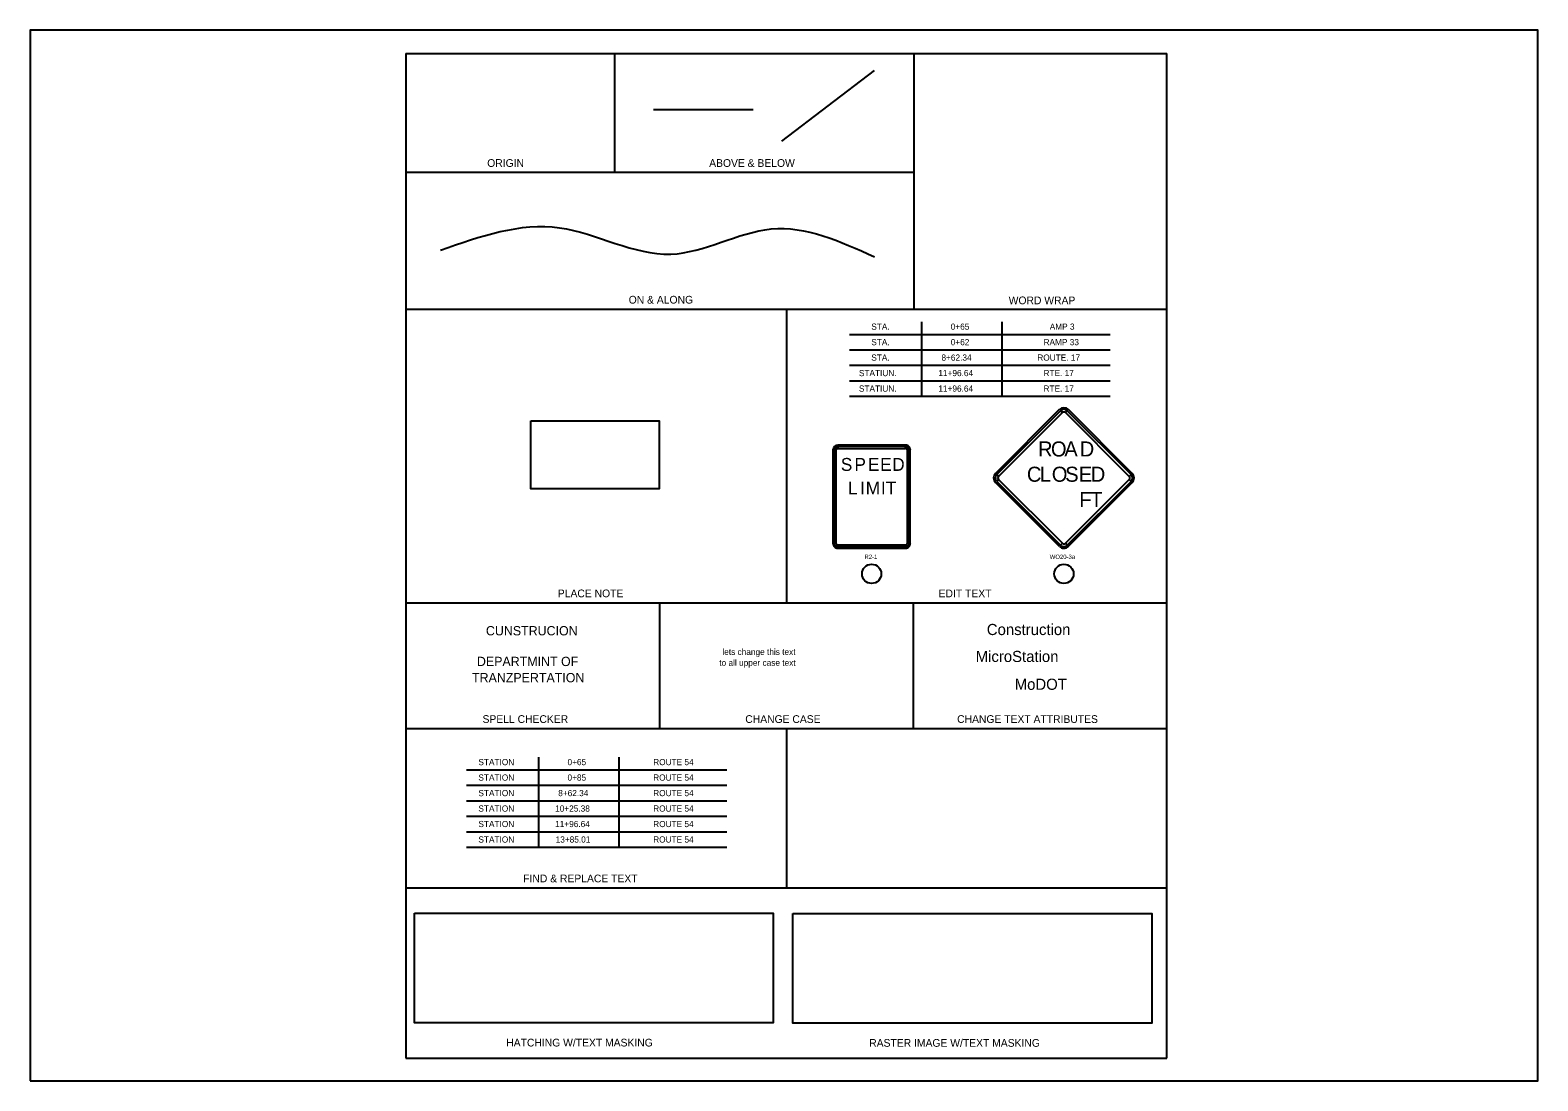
# Model space of a CAD drawing. Extents: x -1524 to 1400, y -1030 to 1008.
import ezdxf

# ---------------------------------------------------------------- set-up
doc = ezdxf.new("R2010")
doc.units = 0
for name, color, linetype in [('Common-Notes', 7, 'Continuous'), ('Draft_Named_Boundary', 7, 'Continuous'), ('Level 1', 7, 'Continuous'), ('Level 2', 7, 'Continuous'), ('Level 25', 7, 'Continuous'), ('Roadway-Signs', 7, 'Continuous')]:
    doc.layers.add(name, color=color, linetype=linetype)

msp = doc.modelspace()

# ---------------------------------------------------------------- linework, layer by layer
at = {"layer": 'Draft_Named_Boundary'}
msp.add_lwpolyline([(-1524.4, -1029.6), (1399.8, -1029.6), (1399.8, 1007.9), (-1524.4, 1007.9)], close=True, dxfattribs=at)
at = {"layer": 'Level 1'}
for p, q in [((-795.5, 962.8), (680.1, 962.8)), ((-795.5, 962.8), (-795.5, -985.9)), ((-391, 962.8), (-391, 732.3)), ((189.4, 962.8), (189.4, 467.2)), ((680.1, -985.9), (680.1, 962.8)), ((-795.5, 732.3), (189.4, 732.3)), ((-795.5, 467.2), (680.1, 467.2)), ((-57.7, 467.2), (-57.7, -102.3)), ((126.8, 433), (126.8, 433)), ((282.6, 433), (282.6, 433)), ((480.5, 433), (480.5, 433)), ((126.8, 403), (126.8, 403)), ((282.6, 403), (282.6, 403)), ((480.5, 403), (480.5, 403)), ((126.8, 373), (126.8, 373)), ((282.6, 373), (282.6, 373)), ((480.5, 373), (480.5, 373)), ((126.8, 343), (126.8, 343)), ((282.6, 343), (282.6, 343)), ((480.5, 343), (480.5, 343)), ((126.8, 312.9), (126.8, 312.9)), ((282.6, 312.9), (282.6, 312.9)), ((480.5, 312.9), (480.5, 312.9)), ((-795.5, -102.3), (680.1, -102.3)), ((-303.6, -102.3), (-303.6, -346)), ((188.3, -102.3), (188.3, -346)), ((-795.5, -346), (680.1, -346)), ((-57.7, -346), (-57.7, -655.1)), ((-795.5, -655.1), (680.1, -655.1)), ((-795.5, -985.9), (680.1, -985.9))]:
    msp.add_line(p, q, dxfattribs=at)
for points in [[(-779.2, -704.7), (-83.3, -704.7), (-83.3, -917.2), (-779.2, -917.2)], [(-45, -705.3), (651, -705.3), (651, -917.8), (-45, -917.8)]]:
    msp.add_lwpolyline(points, close=True, dxfattribs=at)
at = {"layer": 'Level 2'}
for p, q in [((204.7, 442.5), (204.7, 297.9)), ((360.5, 442.5), (360.5, 297.9)), ((65, 418), (570, 418)), ((65, 388), (570, 388)), ((65, 358), (570, 358)), ((65, 328), (570, 328)), ((65, 297.9), (570, 297.9)), ((-538.6, -401.9), (-538.6, -576.5)), ((-382.8, -401.9), (-382.8, -576.5)), ((-678.2, -426.4), (-173.3, -426.4)), ((-678.2, -456.4), (-173.3, -456.4)), ((-678.2, -486.5), (-173.3, -486.5)), ((-678.2, -516.5), (-173.3, -516.5)), ((-678.2, -546.5), (-173.3, -546.5)), ((-678.2, -576.5), (-173.3, -576.5))]:
    msp.add_line(p, q, dxfattribs=at)
at = {"layer": 'Level 25'}
for p, q in [((-66.7, 792.5), (113.2, 930)), ((-315.7, 854.4), (-122.4, 854.4))]:
    msp.add_line(p, q, dxfattribs=at)
msp.add_lwpolyline([(-553.1, 250.6), (-304.6, 250.6), (-304.6, 118.8), (-553.1, 118.8)], close=True, dxfattribs=at)
msp.add_spline([(-728.3, 581.3), (-497.5, 624.9), (-282, 573.6), (-87.1, 622.4), (113, 568.5)], degree=3, dxfattribs=at)
at = {"layer": 'Roadway-Signs'}
for p, q in [((471.7, 272.1), (348, 148.4)), ((473.9, 269.9), (477.6, 266.2)), ((483.5, 266.2), (487.2, 269.9)), ((613.1, 148.4), (489.4, 272.1)), ((32.7, 193.9), (32.7, 12.7)), ((35.3, 193.9), (39, 193.9)), ((173.4, 203.3), (42.1, 203.3)), ((42.1, 197), (42.1, 200.7)), ((173.4, 200.7), (173.4, 197)), ((176.5, 193.9), (180.1, 193.9)), ((182.7, 12.7), (182.7, 193.9)), ((348, 130.7), (471.7, 7)), ((353.9, 142.5), (350.2, 146.2)), ((350.2, 132.9), (353.9, 136.6)), ((489.4, 7), (613.1, 130.7)), ((610.9, 146.2), (607.3, 142.5)), ((607.3, 136.6), (610.9, 132.9)), ((39, 12.7), (35.3, 12.7)), ((42.1, 5.9), (42.1, 9.5)), ((42.1, 3.3), (173.4, 3.3)), ((173.4, 9.5), (173.4, 5.9)), ((180.1, 12.7), (176.5, 12.7)), ((477.6, 12.8), (473.9, 9.2)), ((487.2, 9.2), (483.5, 12.8))]:
    msp.add_line(p, q, dxfattribs=at)
for points in [[(473.9, 269.9), (350.2, 146.2), (353.9, 142.5), (477.6, 266.2), (473.9, 269.9)], [(610.9, 146.2), (487.2, 269.9), (483.5, 266.2), (607.3, 142.5), (610.9, 146.2)], [(35.3, 193.9), (35.3, 12.7), (39, 12.7), (39, 193.9), (35.3, 193.9)], [(173.4, 200.7), (42.1, 200.7), (42.1, 197), (173.4, 197), (173.4, 200.7)], [(180.1, 12.7), (180.1, 193.9), (176.5, 193.9), (176.5, 12.7), (180.1, 12.7)], [(350.2, 132.9), (473.9, 9.2), (477.6, 12.8), (353.9, 136.6), (350.2, 132.9)], [(487.2, 9.2), (610.9, 132.9), (607.3, 136.6), (483.5, 12.8), (487.2, 9.2)], [(42.1, 5.9), (173.4, 5.9), (173.4, 9.5), (42.1, 9.5), (42.1, 5.9)]]:
    msp.add_lwpolyline(points, close=True, dxfattribs=at)
for centre in [(107.7, -46.4), (480.6, -46.4)]:
    msp.add_circle(centre, 18.7, dxfattribs=at)
for centre, radius, start, end in [((480.6, 263.3), 12.5, 45, 134.9997), ((480.6, 263.3), 9.37, 45, 134.9997), ((480.6, 263.3), 4.17, 45, 134.9997), ((42.1, 193.9), 9.38, 90.0002, 179.9998), ((42.1, 193.9), 6.77, 90.0002, 179.9998), ((42.1, 193.9), 3.13, 90.0002, 179.9998), ((173.4, 193.9), 9.38, 0, 90.0002), ((173.4, 193.9), 6.77, 0, 90.0002), ((173.4, 193.9), 3.13, 0, 90.0002), ((356.8, 139.5), 12.5, 134.9997, 225), ((604.3, 139.5), 12.5, 315.0002, 44.9998), ((356.8, 139.5), 9.37, 134.9997, 225), ((356.8, 139.5), 4.17, 134.9997, 225), ((604.3, 139.5), 4.17, 315.0002, 44.9998), ((604.3, 139.5), 9.37, 315.0002, 44.9998), ((42.1, 12.7), 9.38, 179.9998, 270.0001), ((42.1, 12.7), 6.77, 179.9998, 270.0001), ((42.1, 12.7), 3.13, 179.9998, 270.0001), ((173.4, 12.7), 9.38, 270.0001, 0.0003), ((173.4, 12.7), 6.77, 270.0001, 0.0003), ((173.4, 12.7), 3.13, 270.0001, 0.0003), ((480.6, 15.8), 12.5, 225, 315.0002), ((480.6, 15.8), 9.37, 225, 315.0002), ((480.6, 15.8), 4.17, 225, 315.0002)]:
    msp.add_arc(centre, radius, start, end, dxfattribs=at)

# ---------------------------------------------------------------- texts
at = {"layer": 'Common-Notes'}
for s, p in [('HATCHING W/TEXT MASKING', (-601, -962.9)), ('RASTER IMAGE W/TEXT MASKING', (103, -963.5))]:
    msp.add_text(s, height=15, dxfattribs=at).set_placement(p)
at = {"layer": 'Level 1'}
for s, p in [('lets change this text', (-181.8, -203.7)), ('to all upper case text', (-187.8, -224.7))]:
    msp.add_text(s, height=12, dxfattribs=at).set_placement(p)
at = {"layer": 'Level 2'}
for s, height, p in [('ORIGIN', 15, (-637.9, 742.8)), ('ABOVE & BELOW', 15, (-207.4, 742.8)), ('ON & ALONG', 15, (-363.5, 477.7)), ('WORD WRAP', 15, (373.5, 476.4)), ('STA.', 12, (107, 427)), ('0+65', 12, (261.1, 427)), ('AMP 3', 12, (453.1, 427)), ('STA.', 12, (107, 397)), ('0+62', 12, (261.1, 397)), ('RAMP 33', 12, (441.1, 397)), ('STA.', 12, (107, 367)), ('8+62.34', 12, (243.1, 367)), ('ROUTE. 17', 12, (429, 367)), ('STATIUN.', 12, (83, 337)), ('11+96.64', 12, (237.1, 337)), ('RTE. 17', 12, (441, 337)), ('STATIUN.', 12, (83, 306.9)), ('11+96.64', 12, (237.1, 306.9)), ('RTE. 17', 12, (441, 306.9)), ('PLACE NOTE', 15, (-501, -91.8)), ('EDIT TEXT', 15, (237.6, -91.8)), ('Construction', 21.6, (331.1, -165.1)), ('CUNSTRUCION', 18, (-640.4, -165.7)), ('MicroStation', 21.6, (309.5, -217.3)), ('DEPARTMINT OF', 18, (-657.9, -225.2)), ('TRANZPERTATION', 18, (-667.4, -256.7)), ('MoDOT', 21.6, (385.2, -271.3)), ('SPELL CHECKER', 15, (-647, -335.5)), ('CHANGE CASE', 15, (-137.4, -335.5)), ('CHANGE TEXT ATTRIBUTES', 15, (273.5, -335.5)), ('STATION', 12, (-655, -417.4)), ('0+65', 12, (-482.2, -417.4)), ('ROUTE 54', 12, (-316, -417.4)), ('STATION', 12, (-655, -447.4)), ('0+85', 12, (-482.2, -447.4)), ('ROUTE 54', 12, (-316, -447.4)), ('STATION', 12, (-655, -477.5)), ('8+62.34', 12, (-500.2, -477.5)), ('ROUTE 54', 12, (-316, -477.5)), ('STATION', 12, (-655, -507.5)), ('10+25.38', 12, (-506.2, -507.5)), ('ROUTE 54', 12, (-316, -507.5)), ('STATION', 12, (-655, -537.5)), ('11+96.64', 12, (-506.2, -537.5)), ('ROUTE 54', 12, (-316, -537.5)), ('STATION', 12, (-655, -567.5)), ('13+85.01', 12, (-505.2, -567.5)), ('ROUTE 54', 12, (-316, -567.5)), ('FIND & REPLACE TEXT', 15, (-568.1, -644.6))]:
    msp.add_text(s, height=height, dxfattribs=at).set_placement(p)
at = {"layer": 'Roadway-Signs'}
for s, height, p in [('R', 29.2, (430.3, 181.2)), ('O', 29.2, (455.4, 181.2)), ('A', 29.2, (481.4, 181.2)), ('D', 29.2, (511.2, 181.2)), ('S', 25, (47.9, 153.3)), ('P', 25, (74.3, 153.3)), ('E', 25, (100.6, 153.3)), ('E', 25, (124.1, 153.3)), ('D', 25, (147.6, 153.3)), ('C', 29.2, (408.8, 132.2)), ('L', 29.2, (433.9, 132.2)), ('O', 29.2, (457.1, 132.2)), ('S', 29.2, (483.1, 132.2)), ('E', 29.2, (509.5, 132.2)), ('D', 29.2, (532.7, 132.2)), ('L', 25, (62, 107.5)), ('I', 25, (85.5, 107.5)), ('M', 25, (96.2, 107.5)), ('I', 25, (125.7, 107.5)), ('T', 25, (135.1, 107.5)), ('F', 29.2, (510.4, 83.3)), ('T', 29.2, (531.8, 83.3)), ('R2-1', 8.33, (93.8, -17.5)), ('WO20-3a', 8.33, (453.1, -17.5))]:
    msp.add_text(s, height=height, dxfattribs=at).set_placement(p)

doc.saveas('drawing.dxf')
